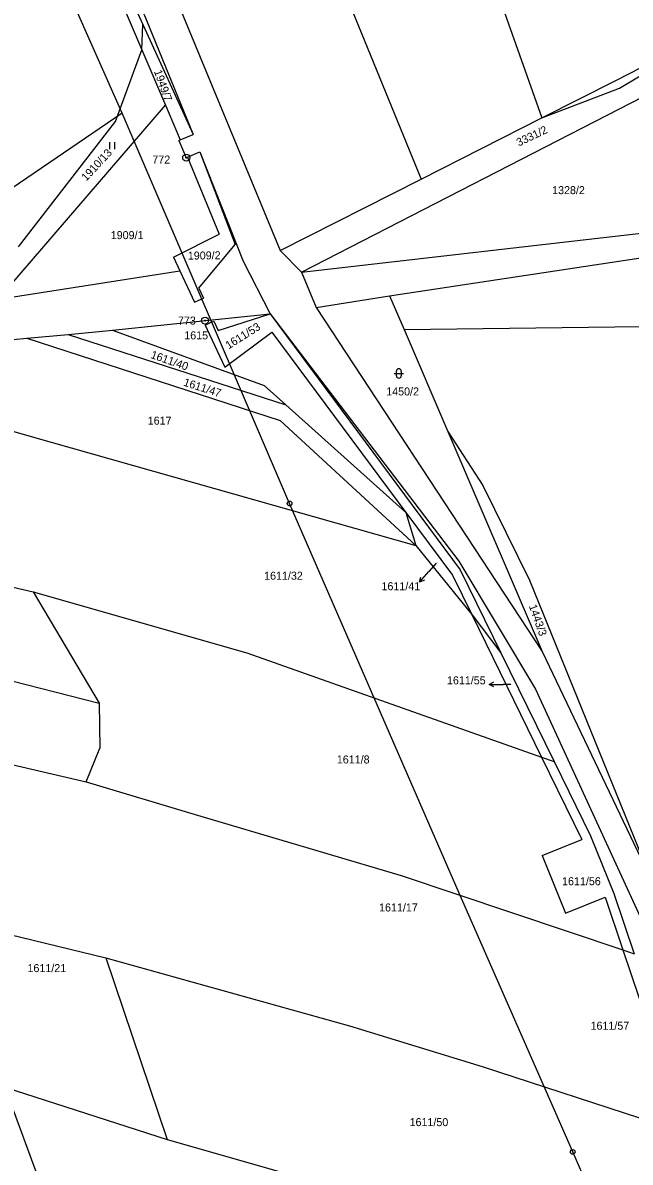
# Model space of a CAD drawing. Extents: x -763205 to -760228, y -1155311 to -1152844.
# Drawn here: x -761138.9 to -761010, y -1155010.6 to -1154768.5 of the extents above; entities that cross this region are included whole.
import ezdxf

# ---------------------------------------------------------------- set-up
doc = ezdxf.new("R2010")
doc.units = 0
for name, color, linetype in [('Vrstva 1', 7, 'Continuous'), ('Vrstva 12', 7, 'Continuous'), ('Vrstva 16', 7, 'Continuous'), ('Vrstva 17', 7, 'Continuous'), ('Vrstva 18', 7, 'Continuous'), ('Vrstva 24', 7, 'Continuous'), ('Vrstva 25', 7, 'Continuous'), ('Vrstva 26', 7, 'Continuous'), ('Vrstva 6', 7, 'Continuous')]:
    doc.layers.add(name, color=color, linetype=linetype)

msp = doc.modelspace()

# ---------------------------------------------------------------- linework, layer by layer
at = {"layer": 'Vrstva 1'}
for p, q in [((-761125.62, -1154716.85), (-761084.26, -1154816.89)), ((-761131.55, -1154721.91), (-761102.76, -1154792.23)), ((-761119.99, -1154759.43), (-761113.67, -1154774.26)), ((-761118.14, -1154758.65), (-761113.45, -1154768.9)), ((-761113.45, -1154768.9), (-761102.76, -1154792.23)), ((-761113.67, -1154774.26), (-761108.66, -1154786.03)), ((-761012.89, -1154780.69), (-761004.98, -1154776.68)), ((-761028.69, -1154788.71), (-761012.89, -1154780.69)), ((-761079.75, -1154821.46), (-761002.36, -1154781.72)), ((-761144.18, -1154827.22), (-761108.66, -1154786.03)), ((-761108.66, -1154786.03), (-761105.53, -1154793.39)), ((-761054.37, -1154801.73), (-761028.69, -1154788.71)), ((-761105.82, -1154793.52), (-761105.53, -1154793.39)), ((-761105.53, -1154793.39), (-761102.76, -1154792.23)), ((-761105.82, -1154793.52), (-761104.24, -1154797.17)), ((-761104.24, -1154797.17), (-761103.98, -1154797.06)), ((-761103.98, -1154797.06), (-761101.36, -1154795.93)), ((-761103.98, -1154797.06), (-761097.23, -1154813.44)), ((-761101.36, -1154795.93), (-761093.88, -1154815.65)), ((-761101.36, -1154795.93), (-761092.13, -1154819.14)), ((-761084.26, -1154816.89), (-761054.37, -1154801.73)), ((-761079.75, -1154821.46), (-760990.06, -1154811.21)), ((-761106.96, -1154818.28), (-761097.23, -1154813.44)), ((-761101.57, -1154824.89), (-761093.88, -1154815.65)), ((-761084.26, -1154816.89), (-761079.75, -1154821.46)), ((-761106.96, -1154818.28), (-761105.58, -1154821.23)), ((-761092.13, -1154819.14), (-761086.4, -1154830.37)), ((-761061.06, -1154826.5), (-761007.69, -1154818.44)), ((-761144.18, -1154827.22), (-761105.58, -1154821.23)), ((-761105.58, -1154821.23), (-761103.46, -1154825.76)), ((-761079.75, -1154821.46), (-761076.68, -1154828.97)), ((-761101.57, -1154824.89), (-761100.6, -1154827)), ((-761103.46, -1154825.76), (-761102.5, -1154827.87)), ((-761101.56, -1154827.44), (-761100.6, -1154827)), ((-761076.68, -1154828.97), (-761061.06, -1154826.5)), ((-761061.06, -1154826.5), (-761057.98, -1154833.68)), ((-761102.5, -1154827.87), (-761101.56, -1154827.44)), ((-761076.68, -1154828.97), (-761028.67, -1154902.1)), ((-761119.91, -1154833.85), (-761086.4, -1154830.37)), ((-761099.26, -1154832.29), (-761098.35, -1154831.88)), ((-761098.35, -1154831.88), (-761097.43, -1154833.91)), ((-761097.43, -1154833.91), (-761086.4, -1154830.37)), ((-761086.4, -1154830.37), (-761046.32, -1154882.86)), ((-761086.4, -1154830.37), (-761046.06, -1154884.7)), ((-761129.3, -1154834.72), (-761119.91, -1154833.85)), ((-761119.91, -1154833.85), (-761087.67, -1154845.54)), ((-761100.24, -1154832.74), (-761099.26, -1154832.29)), ((-761100.24, -1154832.74), (-761099.33, -1154834.77)), ((-761096.07, -1154841.67), (-761086.03, -1154834.22)), ((-761086.03, -1154834.22), (-761057.57, -1154872.58)), ((-761057.98, -1154833.68), (-761048.71, -1154855.32)), ((-761141.01, -1154835.8), (-761138.08, -1154835.53)), ((-761138.08, -1154835.53), (-761129.3, -1154834.72)), ((-761099.33, -1154834.77), (-761096.07, -1154841.67)), ((-761087.67, -1154845.54), (-761083.06, -1154849.68)), ((-761083.06, -1154849.68), (-761057.57, -1154872.58)), ((-761048.71, -1154855.32), (-761028.67, -1154902.1)), ((-761057.57, -1154872.58), (-761047.68, -1154885.9)), ((-761046.32, -1154882.86), (-761030.04, -1154910.11)), ((-761046.06, -1154884.7), (-761037.41, -1154902.36)), ((-761047.68, -1154885.9), (-761043.6, -1154894.23)), ((-761043.6, -1154894.23), (-761028.8, -1154924.5)), ((-761037.41, -1154902.36), (-761026.11, -1154925.45)), ((-761028.67, -1154902.1), (-761005.43, -1154950.75)), ((-761030.04, -1154910.11), (-761002.02, -1154971.17)), ((-761028.8, -1154924.5), (-761020.22, -1154942.03)), ((-761026.11, -1154925.45), (-761018.37, -1154941.27)), ((-761028.66, -1154945.45), (-761020.22, -1154942.03)), ((-761018.37, -1154941.27), (-761013.4, -1154953.52)), ((-761028.66, -1154945.45), (-761023.68, -1154957.7)), ((-761023.68, -1154957.7), (-761015.25, -1154954.28)), ((-761015.25, -1154954.28), (-761011.5, -1154965.48)), ((-761013.4, -1154953.52), (-761009.12, -1154966.28)), ((-761011.5, -1154965.48), (-761004.45, -1154986.52)), ((-761142.75, -1154994.66), (-761131.35, -1155025.67))]:
    msp.add_line(p, q, dxfattribs=at)
at = {"layer": 'Vrstva 12'}
for p, q in [((-761117.82, -1154787.74), (-761152.17, -1154710.36)), ((-761117.82, -1154787.74), (-761176.47, -1154827.58)), ((-761082.28, -1154870.64), (-761117.82, -1154787.74)), ((-761046.28, -1154953.42), (-761082.28, -1154870.64)), ((-761022.16, -1155008.41), (-761046.28, -1154953.42)), ((-760989.63, -1155082.73), (-761022.16, -1155008.41))]:
    msp.add_line(p, q, dxfattribs=at)
at = {"layer": 'Vrstva 16'}
for p, q in [((-761054.696, -1154887.366), (-761052.73, -1154885.1)), ((-761051.17, -1154883.3), (-761052.73, -1154885.1)), ((-761039.91, -1154909.061), (-761036.91, -1154909.06)), ((-761035.28, -1154909.06), (-761036.91, -1154909.06))]:
    msp.add_line(p, q, dxfattribs=at)
for points in [[(-761053.663, -1154886.938), (-761054.696, -1154887.366), (-761054.418, -1154886.283)], [(-761038.91, -1154909.56), (-761039.91, -1154909.061), (-761038.91, -1154908.56)]]:
    msp.add_lwpolyline(points, dxfattribs=at)
at = {"layer": 'Vrstva 24'}
for centre, radius in [((-761104.24, -1154797.17), 0.75), ((-761104.24, -1154797.17), 0.1), ((-761100.24, -1154831.78), 0.75), ((-761100.24, -1154831.78), 0.1)]:
    msp.add_circle(centre, radius, dxfattribs=at)
at = {"layer": 'Vrstva 25'}
for p, q in [((-761120.43, -1154795.38), (-761120.43, -1154793.88)), ((-761119.43, -1154795.38), (-761119.43, -1154793.88)), ((-761060.09, -1154843), (-761058.09, -1154843)), ((-761059.59, -1154843.5), (-761059.59, -1154842.5)), ((-761058.59, -1154842.5), (-761058.59, -1154843.5))]:
    msp.add_line(p, q, dxfattribs=at)
for centre, start, end in [((-761059.09, -1154842.5), 0, 180), ((-761059.09, -1154843.5), 180, 0)]:
    msp.add_arc(centre, 0.5, start, end, dxfattribs=at)
at = {"layer": 'Vrstva 26'}
for centre in [(-761082.28, -1154870.64), (-761022.16, -1155008.41)]:
    msp.add_circle(centre, 0.5, dxfattribs=at)
at = {"layer": 'Vrstva 6'}
for p, q in [((-761047.7, -1154735.12), (-761028.69, -1154788.71)), ((-761081.29, -1154735.85), (-761054.37, -1154801.73)), ((-761012.22, -1154782.37), (-760972.57, -1154758.7)), ((-761113.67, -1154774.26), (-761113.45, -1154768.9)), ((-761119.24, -1154789.5), (-761113.67, -1154774.26)), ((-761028.69, -1154788.71), (-761012.22, -1154782.37)), ((-761139.87, -1154816.13), (-761119.24, -1154789.5)), ((-761057.98, -1154833.68), (-761007.65, -1154833.01)), ((-761138.08, -1154835.53), (-761084.29, -1154853.01)), ((-761129.3, -1154834.72), (-761083.06, -1154849.68)), ((-761164.75, -1154848.59), (-761137.17, -1154856.41)), ((-761084.29, -1154853.01), (-761055.46, -1154879.58)), ((-761048.71, -1154855.32), (-761041.24, -1154866.82)), ((-761137.17, -1154856.41), (-761055.46, -1154879.58)), ((-761041.24, -1154866.82), (-761031.31, -1154886.96)), ((-761057.57, -1154872.58), (-761055.46, -1154879.58)), ((-761182.62, -1154878.7), (-761136.75, -1154889.41)), ((-761055.46, -1154879.58), (-761043.6, -1154894.23)), ((-761031.31, -1154886.96), (-761005.43, -1154950.75)), ((-761136.75, -1154889.41), (-761122.76, -1154913.05)), ((-761136.75, -1154889.41), (-761091.38, -1154902.34)), ((-761043.6, -1154894.23), (-761037.41, -1154902.36)), ((-761177.67, -1154899.07), (-761122.76, -1154913.05)), ((-761091.38, -1154902.34), (-761028.8, -1154924.5)), ((-761122.76, -1154913.05), (-761122.62, -1154922.65)), ((-761170.25, -1154919.38), (-761125.49, -1154929.76)), ((-761125.49, -1154929.76), (-761122.62, -1154922.65)), ((-761028.8, -1154924.5), (-761026.11, -1154925.45)), ((-761125.49, -1154929.76), (-761102.32, -1154936.72)), ((-761102.32, -1154936.72), (-761058.58, -1154949.69)), ((-761058.58, -1154949.69), (-761011.5, -1154965.48)), ((-761155.88, -1154958.78), (-761121.29, -1154967.13)), ((-761121.29, -1154967.13), (-761108.27, -1155005.79)), ((-761121.29, -1154967.13), (-761069.59, -1154981.61)), ((-761011.5, -1154965.48), (-761009.12, -1154966.28)), ((-761069.59, -1154981.61), (-761041.41, -1154990.24)), ((-761041.41, -1154990.24), (-760998.5, -1155004.29)), ((-761142.75, -1154994.66), (-761108.27, -1155005.79)), ((-761108.27, -1155005.79), (-761069.13, -1155016.91))]:
    msp.add_line(p, q, dxfattribs=at)

# ---------------------------------------------------------------- texts
at = {"layer": 'Vrstva 16'}
for s, p in [('1611/41', (-761062.777, -1154889.07)), ('1611/55', (-761048.871, -1154909.06)), ('1611/57', (-761018.377, -1154982.44))]:
    msp.add_text(s, height=1.7, dxfattribs=at).set_placement(p)
at = {"layer": 'Vrstva 17'}
for s, p in [('772', (-761111.438, -1154798.42)), ('773', (-761105.994, -1154832.63))]:
    msp.add_text(s, height=1.7, dxfattribs=at).set_placement(p)
at = {"layer": 'Vrstva 18'}
for s, rotation, p in [('1949/7', 289.74476, (-761111.117, -1154778.83)), ('3331/2', 25.55392, (-761033.626, -1154794.818)), ('1910/13', 47.09713, (-761125.463, -1154802.272)), ('1909/2', 0.74484, (-761103.887, -1154818.835)), ('1611/53', 32.25753, (-761095.238, -1154837.92)), ('1611/40', 340.62341, (-761111.92, -1154839.7)), ('1611/47', 342.22769, (-761104.956, -1154845.57)), ('1443/3', 289.34369, (-761031.49, -1154892.411))]:
    msp.add_text(s, height=1.7, rotation=rotation, dxfattribs=at).set_placement(p)
for s, height, p in [('1328/2', 1.7, (-761026.537, -1154804.92)), ('1909/1', 1.7, (-761120.267, -1154814.47)), ('1615', 1.7, (-761104.657, -1154835.77)), ('1450/2', 1.7, (-761061.767, -1154847.68)), ('1617', 1.7, (-761112.417, -1154853.89)), ('1611/32', 1.7, (-761087.697, -1154886.83)), ('1611/41', 0.1, (-761051.147, -1154883.3)), ('1611/55', 0.1, (-761035.257, -1154909.06)), ('1611/8', 1.7, (-761072.257, -1154925.87)), ('1611/56', 1.7, (-761024.427, -1154951.74)), ('1611/17', 1.7, (-761063.287, -1154957.32)), ('1611/21', 1.7, (-761137.947, -1154970.2)), ('1611/50', 1.7, (-761056.807, -1155002.92))]:
    msp.add_text(s, height=height, dxfattribs=at).set_placement(p)

doc.saveas('drawing.dxf')
